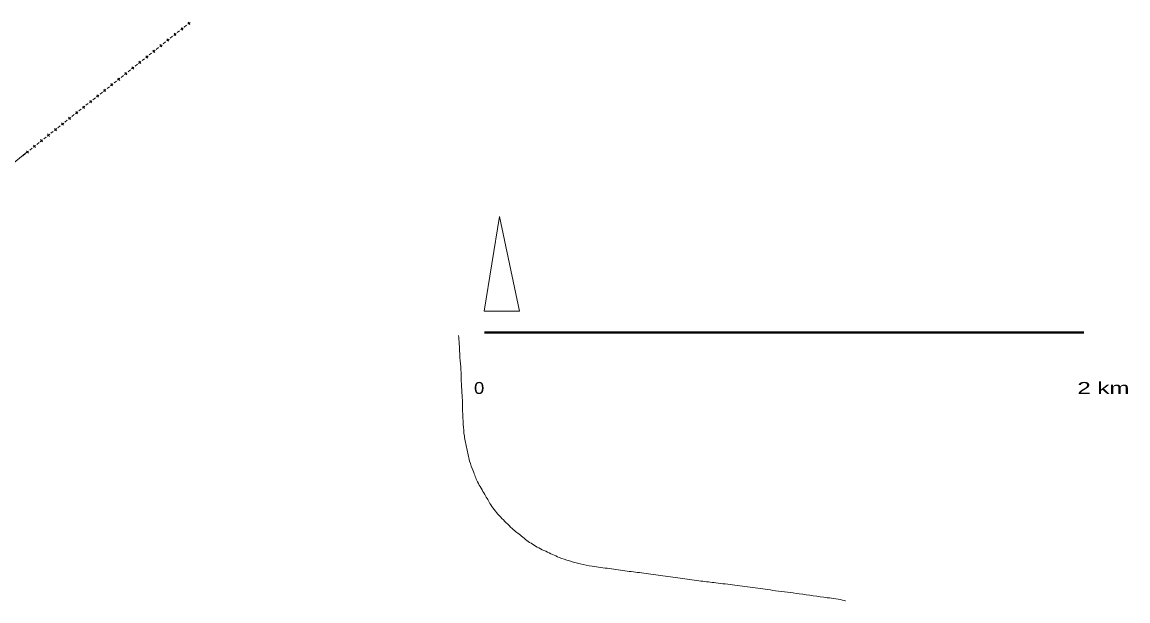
# Model space of a CAD drawing. Extents: x 476989 to 498418, y 4381813 to 4416555.
# Drawn here: x 487660 to 491352, y 4381813 to 4383746 of the extents above; entities that cross this region are included whole.
import ezdxf

# ---------------------------------------------------------------- set-up
doc = ezdxf.new("R2010")
doc.units = 0
doc.header["$LTSCALE"] = 20
for name, color, linetype, lineweight in [('14', 7, 'Continuous', 40), ('34', 7, 'Continuous', 13), ('39', 7, 'Continuous', 13), ('63', 7, 'Continuous', 13)]:
    doc.layers.add(name, color=color, linetype=linetype, lineweight=lineweight)

msp = doc.modelspace()

# ---------------------------------------------------------------- linework, layer by layer
at = {"layer": '14'}
for p, q in [((489204.19, 4382709.6), (490204.19, 4382709.6)), ((490204.54, 4382709.6), (491204.54, 4382709.6))]:
    msp.add_line(p, q, dxfattribs=at)
at = {"layer": '34'}
for p, q in [((488209.68, 4383736.23), (488201.86, 4383730)), ((488221.41, 4383745.58), (488213.59, 4383739.35)), ((488220.62, 4383738.56), (488214.39, 4383746.38)), ((488162.78, 4383698.85), (488154.96, 4383692.62)), ((488174.51, 4383708.2), (488166.69, 4383701.97)), ((488173.71, 4383701.17), (488167.48, 4383708.99)), ((488186.23, 4383717.54), (488178.41, 4383711.31)), ((488197.96, 4383726.89), (488190.14, 4383720.66)), ((488197.17, 4383719.86), (488190.93, 4383727.68)), ((488115.87, 4383661.47), (488108.05, 4383655.24)), ((488127.6, 4383670.82), (488119.78, 4383664.58)), ((488126.81, 4383663.79), (488120.58, 4383671.61)), ((488139.32, 4383680.16), (488131.5, 4383673.93)), ((488151.05, 4383689.51), (488143.23, 4383683.28)), ((488150.26, 4383682.48), (488144.03, 4383690.3)), ((488068.97, 4383624.09), (488061.15, 4383617.85)), ((488080.7, 4383633.43), (488072.88, 4383627.2)), ((488079.9, 4383626.41), (488073.67, 4383634.23)), ((488092.42, 4383642.78), (488084.6, 4383636.54)), ((488104.15, 4383652.13), (488096.33, 4383645.89)), ((488103.36, 4383645.1), (488097.12, 4383652.92)), ((488022.06, 4383586.7), (488014.24, 4383580.47)), ((488033.79, 4383596.05), (488025.97, 4383589.82)), ((488033, 4383589.02), (488026.76, 4383596.85)), ((488045.51, 4383605.39), (488037.69, 4383599.16)), ((488057.24, 4383614.74), (488049.42, 4383608.51)), ((488056.45, 4383607.72), (488050.22, 4383615.54)), ((487975.15, 4383549.32), (487967.33, 4383543.09)), ((487986.88, 4383558.67), (487979.06, 4383552.44)), ((487986.09, 4383551.64), (487979.86, 4383559.46)), ((487998.61, 4383568.01), (487990.79, 4383561.78)), ((488010.34, 4383577.36), (488002.52, 4383571.13)), ((488009.54, 4383570.33), (488003.31, 4383578.15)), ((487939.98, 4383521.29), (487932.16, 4383515.05)), ((487939.19, 4383514.26), (487932.95, 4383522.08)), ((487951.7, 4383530.63), (487943.88, 4383524.4)), ((487963.43, 4383539.98), (487955.61, 4383533.74)), ((487962.64, 4383532.95), (487956.41, 4383540.77)), ((487893.07, 4383483.9), (487885.25, 4383477.67)), ((487892.28, 4383476.88), (487886.05, 4383484.7)), ((487904.8, 4383493.25), (487896.98, 4383487.01)), ((487916.53, 4383502.59), (487908.71, 4383496.36)), ((487915.73, 4383495.57), (487909.5, 4383503.39)), ((487928.25, 4383511.94), (487920.43, 4383505.7)), ((487846.17, 4383446.52), (487838.35, 4383440.29)), ((487845.37, 4383439.49), (487839.14, 4383447.31)), ((487857.89, 4383455.86), (487850.07, 4383449.63)), ((487869.62, 4383465.21), (487861.8, 4383458.98)), ((487868.83, 4383458.19), (487862.59, 4383466.01)), ((487881.34, 4383474.55), (487873.52, 4383468.32)), ((487799.26, 4383409.14), (487791.44, 4383402.91)), ((487798.47, 4383402.11), (487792.24, 4383409.93)), ((487810.98, 4383418.48), (487803.16, 4383412.25)), ((487822.72, 4383427.83), (487814.89, 4383421.6)), ((487821.92, 4383420.8), (487815.69, 4383428.62)), ((487834.44, 4383437.17), (487826.62, 4383430.94)), ((487752.36, 4383371.76), (487744.54, 4383365.52)), ((487751.56, 4383364.73), (487745.33, 4383372.55)), ((487764.08, 4383381.1), (487756.26, 4383374.87)), ((487775.81, 4383390.45), (487767.99, 4383384.21)), ((487775.02, 4383383.42), (487768.78, 4383391.24)), ((487787.53, 4383399.79), (487779.71, 4383393.56)), ((487705.45, 4383334.37), (487697.63, 4383328.14)), ((487704.66, 4383327.35), (487698.42, 4383335.17)), ((487717.17, 4383343.72), (487709.35, 4383337.48)), ((487728.9, 4383353.06), (487721.08, 4383346.83)), ((487728.11, 4383346.04), (487721.88, 4383353.86)), ((487740.63, 4383362.41), (487732.81, 4383356.17)), ((487670.27, 4383306.33), (487662.45, 4383300.1)), ((487676.62, 4383311.39), (487674.18, 4383309.45)), ((487676.63, 4383314.4), (487674.97, 4383316.48)), ((487682, 4383315.68), (487676.62, 4383311.39)), ((487681.2, 4383308.65), (487676.63, 4383314.4)), ((487693.72, 4383325.02), (487685.9, 4383318.79))]:
    msp.add_line(p, q, dxfattribs=at)
msp.add_lwpolyline([(487676.62, 4383311.4), (487577, 4383232), (487304, 4383028), (487077, 4382869), (487054, 4382844), (487031, 4382851), (487023, 4382817), (486778, 4382653), (486740, 4382634), (486629, 4382532), (486583, 4382537), (486557, 4382471), (486289, 4382313), (486283, 4382292), (486265, 4382283)], dxfattribs=at)
at = {"layer": '39'}
msp.add_spline([(489117.55, 4382698.88), (489119.92, 4382672.68), (489122.01, 4382625.33), (489125.29, 4382585.13), (489126.65, 4382547.13), (489128.77, 4382508.18), (489130.39, 4382475.59), (489130.93, 4382447.55), (489133.21, 4382401.71), (489136.74, 4382363.61), (489144.72, 4382321.33), (489154.17, 4382280.07), (489166.23, 4382246.73), (489180.75, 4382210.53), (489205.22, 4382168.24), (489224.8, 4382133.94), (489257.72, 4382093.12), (489296.35, 4382054.96), (489327.82, 4382028.88), (489364.04, 4382002), (489408.28, 4381978.37), (489453.5, 4381958.06), (489487.73, 4381946.36), (489523.65, 4381936.12), (489563.73, 4381928.23), (489620.66, 4381920.7), (489680.32, 4381912.26), (489735.44, 4381905.59), (489799.91, 4381896.95), (489865.43, 4381887.81), (489926.74, 4381879.18), (489976.6, 4381873.08), (490039.39, 4381865.3), (490107.84, 4381856.38), (490175.25, 4381846.83), (490254.89, 4381836.5), (490348.33, 4381823.47), (490406.14, 4381813.57), (490409.06, 4381812.73)], degree=3, dxfattribs=at)
at = {"layer": '63'}
msp.add_lwpolyline([(489203.09, 4382781.04), (489321.4, 4382781.04), (489253.79, 4383096.75)], close=True, dxfattribs=at)

# ---------------------------------------------------------------- texts
at = {"layer": '14'}
for s, width, p in [('0', 1.15, (489169.03, 4382504.01)), ('2 km', 1.5, (491183.4, 4382504.01))]:
    msp.add_text(s, height=40, dxfattribs=dict(at, width=width)).set_placement(p)

doc.saveas('drawing.dxf')
